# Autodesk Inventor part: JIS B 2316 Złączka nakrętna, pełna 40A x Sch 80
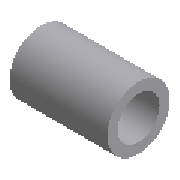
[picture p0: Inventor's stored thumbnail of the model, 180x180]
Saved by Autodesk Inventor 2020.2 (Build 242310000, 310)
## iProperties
Manager: www.cadconsulting.pl
Company: Fabian Stasiak CAD Consulting
Created: 2014-02
Part Number: JIS B 2316 Złączka nakrętna, pełna 40A x Sch 80
Material: Stal
Description: Złączka nakrętna
Document SubType Name: Modeling
Standard: JIS B 2316
Designer: F.Stasiak
Standards Organization: JIS
Language: pl-PL
Size Designation: 40A x Sch 80
Categories: <MemberInstance><Categories><Category DisplayName="Rury cienko- i grubościenne" InternalName="4347fa0f-2144-441d-94cd-e3e15c92b736" Mnemonic="TUBEANDPIPE"><Cate
Density: 1 g/cm^3
Appearance: Płyta
Catalog Web Link: www.expertbooks.pl
NAME: PIPING: JIS B 2316 Full Coupling
DATA: <meta><inlinegroups number="1" deflen="2.56"></inlinegroups><connections number="2"></connections><angles><a>3.14159265358979</a></angles></meta>
IsCustomPart: 0
Author: F.Stasiak
Subject: Zbiór ćwiczeń. Autodesk Inventor 2020. Kurs Professional
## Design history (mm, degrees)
sketch "Sketch1"
  geometry: L1 (0, 0)-(38.1, 0); L2 (38.1, 0)-(38.1, 24.55); L3 (38.1, 24.55)-(38.1, 30.15); L4 (38.1, 30.15)-(0, 30.15); L5 (19.05, 0)-(19.05, 30.15); L6 (38.1, 24.55)-(25.4, 24.55); L7 (25.4, 24.55)-(25.4, 20.6); L8 (25.4, 20.6)-(12.7, 20.6); L9 (0, 24.55)-(0, 30.15); L10 (0, 24.55)-(12.7, 24.55); L11 (12.7, 24.55)-(12.7, 20.6); L12 (0, 0)-(0, 24.55); L13 (12.7, 20.6)-(12.7, 0); L14 (25.4, 20.6)-(25.4, 0); 1 further point
  constraints: 28 end point, 4 perpendicular, 4 symmetric about line, 2 horizontal, 2 midpoint, 2 parallel, 2 point on line, 1 coincident, 1 collinear, 4 other
  dimensions: "d0" = 49.1 diameter of L2.end L1 (= S); "d1" = 41.2 diameter of L8 L1 (= D); "d2" = 60.3 diameter of L4 L1 (= S + 2 x T); "d4" = 12.7 distance of L7.end L8.end (= E1); "d5" = 12.7 distance of L9.start L10.end (= C1)
revolve "Revolution1" sketch "Sketch1" stored, may be unused: angle "d10" = 90 deg
workpoint "Work Point1"
workpoint "Work Point2"
workaxis "Work Axis1"
workpoint "Work Point3"
workaxis "Work Axis2"
workpoint "Work Point4"
body "Solid1"
other parameters: "S" = 49.1 [user parameter; used in 2 equation terms], "E1" = 12.7 [user parameter; used in 1 equation term], "D" = 41.2 [user parameter; used in 1 equation term], "C1" = 12.7 [user parameter; used in 1 equation term], "T" = 5.6 [user parameter; used in 1 equation term], "Size_Designation" = 12.345 [user parameter]
